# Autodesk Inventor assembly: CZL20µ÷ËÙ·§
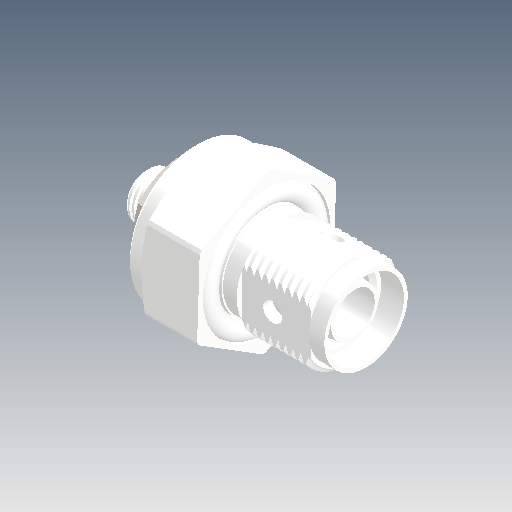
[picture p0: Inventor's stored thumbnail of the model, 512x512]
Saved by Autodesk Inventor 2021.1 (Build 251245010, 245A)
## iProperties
Created: 2021-05
Part Number: CZL20µ÷ËÙ·§
Document SubType Name: Assembly
Designer: user
Author: user
Revision Number: ÈÎºÎ
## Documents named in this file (4)
- D:\Vault_2016\Projekty\Clamptek\Hydraulic\CHLC\CHLC-50\Inventor\CHLC-FAMT50\CZL20µ÷ËÙ·§.iam
- D:\Vault_2016\Projekty\Clamptek\Hydraulic\CHLC\CHLC-50\Inventor\CHLC-FAMT50\20·§Ìå.ipt
- D:\Vault_2016\Projekty\Clamptek\Hydraulic\CHLC\CHLC-50\Inventor\CHLC-FAMT50\20µ÷ËÙ¸Ë.ipt
- D:\Vault_2016\Projekty\Clamptek\Hydraulic\CHLC\CHLC-50\Inventor\CHLC-FAMT50\hex thin nuts-grades ab-chamfered gb(GB_FASTENER_NUT_STNAB M6-S).ipt
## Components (3 placed, 3 different names)
1. 20·§Ìå_19
2. 20µ÷ËÙ¸Ë_20
3. hex thin nuts-grades ab-chamfered gb(GB_FASTENER_NUT_STNAB M6-S)_21
